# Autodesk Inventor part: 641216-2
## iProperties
Shininess: 64.0
Length Units: 11272
Angle Units: 11279
Time Units: 11290
Mass Units: 11286
Length Display Precision: 3
Angle Display Precision: 2
Compacted: True
Part Number: 641216-2
Document SubType Name: Modeling
Created: 2004-02
Designer: RRomano
Manufacturer: Standard
Standards Organization: Custom
Description: MTA100 RT ANGLE
Vendor: AMP
Density: 0.0
Volumn: 0.0
Area: 0.0
PropertySet Name: Model Information
Control State: 0
Master: False
Checked Out: False
Author: RRomano
Title: CONNECTOR MTA 100 STYLE RT ANGLE
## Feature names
1. Sweep1
2. Chamfer1
3. Extrusion1
4. Rectangular Pattern1
5. Extrusion3
6. Extrusion4
7. Extrusion5
8. Rectangular Pattern2
9. Extrusion6
10. Extrusion7
11. Rectangular Pattern3
